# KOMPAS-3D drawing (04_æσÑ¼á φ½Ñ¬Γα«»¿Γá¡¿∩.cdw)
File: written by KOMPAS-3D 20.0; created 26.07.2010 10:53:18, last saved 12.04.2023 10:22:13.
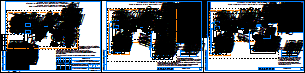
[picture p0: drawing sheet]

Sheets 1-3: A3, landscape

Document properties: Автор: Силов Дмитрий Дмитриевич; Проверил: Тарасов; Форматы листов документа: 3xA3; Полное имя файла: \\s-tech\depts\Отдел_ПКО\Проекты\Типовые проекты МКД 2023\!Типовой проект\1_Типовой проект МКД_RS-485\04_Схема электропитания.cdw

Title block, sheet 1: Наименование: Типовой проект ИСУЭ / многоквартирного дома с использлованием / проводного канала связи RS-485; designation: ВЛСТ 1277.01.001 C5; Материал: Схема подключения электропитания; scale: 1:5; sheet number: 1; Количество листов документа: 1; organisation: АО ГК "Системы и Технологии"; Форматы листов документа: A3; Литера: К; Литера: 1; stored path: Z:\!Оборудование СТ\АСУ НО\Модификации\50А\Новое\Сборочный чертеж.cdw; Разработал: Воронина; Утвердил: Шмончев; cell 302: Система учета электроэнергии / (с организацией удаленного сбора данных) потребителей; cell 303: Типовой проект ИСУЭ многоквартирного дома / с использованием проводного канала связи RS-485; cell 320: Р
Title block, sheet 2: sheet number: 2; sheet number: 3; stored path: \\s-tech\Depts\Отдел_ПКО\Проекты\Русснефть\Типовые шкафы учета\4 счетчика 0,4 кВ 2СШ\Схема.cdw; designation, second copy: ВЛСТ 1277.01.001 C5-
Title block, sheet 3: stored path: \\s-tech\depts\Отдел_ПКО\Проекты\Типовые проекты МКД 2023\!Типовой проект\1_Типовой проект МКД_RS-485\5_Схема электропитания.cdw

Referenced files in \\Helios\отдел_пко\Общая папка Компас\_Addons\Signatures\: Signatures.lfr|Тарасов, Signatures.lfr, Signatures.lfr|Шмончев
Referenced files in C:\Program Files\ASCON\KOMPAS-3D V13\Libs\_Addons\Signatures\: Signatures.lfr
Referenced files: qlkzkl.frw, hsklda.frw, jndvba.frw
Referenced files in Y:\Общая папка Компас\_Addons\Signatures\: Signatures.lfr|Голдина, Signatures.lfr
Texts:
  Тарасов
  Голдина
  Table Heading
  Table Contents
  Normal
  Материал-Предприятие
  Лит-Масса-Масштаб
  ООббыыччнныыйй
  Definition Term
  Definition List
  Address
  Blockquote
  Preformatted
  Courier New
  z-Bottom of Form
  z-Top of Form
  ISOCPEUR
  Centerline
  Outline
  Таблица 1 - Перечень основного оборудования
  № поз.
  Колич.
  Электронный переключатель фаз ПЭФ-301
  Блок питания 30 Вт (ВЛСТ 1000.10.002)
  Интеллектуальный контроллер SM160-02M
  Коммутатор Planet ISW-800T
  ХТ1
  QF1, QF2
  QF3, QF4
  ХТ2
  Преобразователь Ethernet/4xRS-485
  Шина РЕ "земля" на DIN-изоляторе ШНИ-6х9-18-Д-Ж
  Клеммник ("N") в составе:
  Автоматический выключатель ВА47-29 2Р 6А х-ка С
  Автоматический выключатель ВА47-29 2Р 10А х-ка С
  HMM.2/2+2(Ex)i, проходной зажим 2,5 кв.мм синий 2 ввод/2 вывода
  Клеммник ("=24В") в составе:
  HMM.2/2+2GR(Ex), проходной зажим 2,5 кв.мм серый 2 ввод/2 вывода
  Перемычка втычная Изолированная 2 полюса Красная Шаг 5,2мм
  Провод белый ПуГВ 1х2,5
  Провод синий ПуГВ 1х2,5
  Провод белый ПуГВ 1х0,75
  Провод синий ПуГВ 1х0,75
  Провод желто-зеленый ПуГВ 1х4
  Электрощитовая
  QF2
  QF1
  Переключатель
  фаз
  Шкаф УСПД
  Интеллектуальный контроллер SM160-02М
  COM4
  COM3
  COM2
  COM1
  Питание
  RS-232
  RxD
  TxD
  GND
  ТС2-
  ТС1-
  ТС+
  GSM
  Etherhet
  USB-A
  Коммутаттор
  Planet
  ISW-800T
  DC1
  Преобразователь
  Ethernet/
  МКД
  1. При монтаже оборудования руководствоваться
  соответствующими разделами эксплуатационной
  документации оборудования.
  Таблица 2 - Перечень основного оборудования
  ХТ3
  ХТ4
  Клеммник ("L,N") в составе:
  Клеммник ("=24В для оборудования в шкафу") в составе:
  Клеммник ("=24В для АРК") в составе (max 3 линии):
  Клеммник ("=24В для АРК") в составе (max 7 линий):
  Клеммник ("=24В для АРК") в составе (max 11 линий):
  Перемычка втычная Изолированная 3 полюса Красная Шаг 5,2мм
  Клеммник ("=24В для АРК") в составе (max 15 линий):
  Перемычка втычная Изолированная 5 полюсов Красная Шаг 5,2мм
  3. Количество преобразователей Ethernet/4xRS-485
  зависит от количества линий RS-485.
  4. Если количество преобразователей Ethernet/4хRS-485
  больше 5 шт, то требуется увеличение мощности блока
  питания.
  Мощность блока, Вт
  Количество АРК, шт
  1. Позиции пронумерованы согласно таблице 2 - Перечень
  основного оборудования.
  2. Выбор мощности блока питания для питания АРК:
  АРК 6 этаж
  АРК 12 этаж
  АРК 17 этаж
  АРК N
  ... электр. стояк
  Таблица 3 - Перечень основного оборудования
  Преобразователь линии ВЛСТ 217.00.000-04
  3. Подключение питания для АРК осуществить кабелем
  Hyperline FTP4-C5E-SOLID-OUTDOOR-40.  Расключение
  в клеммник осуществить скруткой двух жил кабеля.
  4. Количество клемм в клеммнике XT4 меняется в
  зависимости от количества питающих линий АРК.
  5. Маркировка кабеля приведена согласно Кабельному
  журналу ВЛСТ 1277. 01. 001 С6.
  АРК 2
  АРК 3
  АРК 4
  АРК 5
  1. Позиции пронумерованы согласно таблице 3 - Перечень
  МY-Х-N(Р)
  2. Позиции пронумерованы согласно таблице 1 - Перечень основного оборудования.
  3. Количество преобразователей Ethernet/4xRS-485 зависит от количества линий RS-485.
  4. Если количество преобразователей Ethernet/4хRS-485 больше 5 шт, то требуется увеличение
  мощности блока питания.
  5. Маркировка кабеля приведена согласно Кабельному журналу ВЛСТ 1277. 01. 002 С6 (ВЛСТ 1277.
  АРК 1
  Вариант 1. Многоквартирный дом с этажностью - до 5
  Щит со счетчиками на площадке этажа, активная разветвительная коробка RS-485
  Вариант 2. Многоквартирный дом с этажностью - 9
  Два щита со счетчиками на площадке этажа, пассивная разветвительная коробка RS-485
  Вариант 4. Многоквартирный дом с этажностью - 14-18
  Щит со счетчиками на площадке этажа, пассивная разветвительная коробка RS-485
  Вариант 3. Многоквартирный дом с этажностью - 14-18
  ВРУ №2
  ВРУ №1
  Автоматический
  выключатель
  QF3
  Точка
  подключения
  QF4
  5. Подключение питания для АРК осуществить кабелем Hyperline FTP4-C5E-SOLID-OUTDOOR-40.  Расключение
  6. Количество клемм в клеммнике XT4 меняется в зависимости от количества питающих линий АРК.
  7. Маркировка кабеля приведена согласно Кабельному журналу ВЛСТ 1277. 01. 003 С6.
  линии
  ВЛСТ 217.00.000-04
  Антенна GSM
  Блок питания
  POLYLINE_STYLE_0.30_RGB_0_255_255
  SLD-Сплошная_RGB_0_255_255_THICK_0.3
  POLYLINE_STYLE_0.25_RGB_0_0_0
  тон пунк.0.5-0,5
  JIS_02_2.0_RGB_255_0_255_SC_3_THICK_0.13
  Красная
  POLYLINE_STYLE_0.40_RGB_0_0_255
  POLYLINE_STYLE_0.30_RGB_0_0_255
  POLYLINE_STYLE_0.20_RGB_0_0_0
  POLYLINE_STYLE_0.20_RGB_0_255_255
  Штриховая 2.0х1.0
  Стили документа
  Разраб.
  Утв.
  03 Рабочие чертежи основного комплекта. ГОСТ Р 21.1101-2009 Ф3
  05 Чертежи строительных изделий. Посл. листы. ГОСТ Р 21.1101-2009 Ф6
Dimensions and other numbers on the sheet: 5и0; 4и0; 1; 2; 3; 1 шт.; 4; 5; 6; 1-5 шт.; 1 компл.; 2 шт.; 7; 8; 9; 10; 11; 12; 1   2  3   4   5  6; 24 В; 4хRS-485 №1; 4хRS-485 №5; 3 шт.; 4 шт.; 30; 50; 18; 100; 37; 1 электр. стояк; 1 подъезд; 1 этаж; 01. 003 С6).; 2 подъезд; 3 подъезд; 4 подъезд; 5 подъезд; 220В; 1   2   3   4; 220 В; 6   5; 0,5-0,5; 0,5-0,5 Основная; 1:5; 03.23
